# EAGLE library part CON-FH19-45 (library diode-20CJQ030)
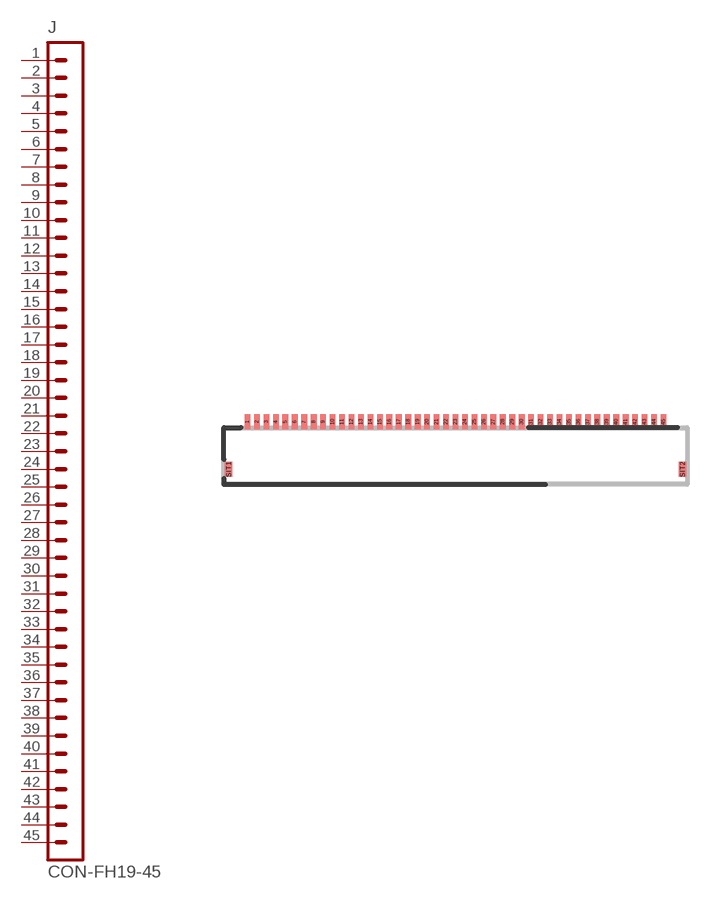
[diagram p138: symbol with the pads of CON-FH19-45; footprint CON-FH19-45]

Designator prefix J

## CON-FH19-45  [CON-FH19-45]
1  1  pas
2  2  pas
3  3  pas
4  4  pas
5  5  pas
6  6  pas
7  7  pas
8  8  pas
9  9  pas
10  10  pas
11  11  pas
12  12  pas
13  13  pas
14  14  pas
15  15  pas
16  16  pas
17  17  pas
18  18  pas
19  19  pas
20  20  pas
21  21  pas
22  22  pas
23  23  pas
24  24  pas
25  25  pas
26  26  pas
27  27  pas
28  28  pas
29  29  pas
30  30  pas
31  31  pas
32  32  pas
33  33  pas
34  34  pas
35  35  pas
36  36  pas
37  37  pas
38  38  pas
39  39  pas
40  40  pas
41  41  pas
42  42  pas
43  43  pas
44  44  pas
45  45  pas

## Footprint CON-FH19-45 (pad centres in mm)
smd 0.3 x 0.8: 1 -10.25,2.54; 2 -9.75,2.54; 3 -9.25,2.54; 4 -8.75,2.54; 5 -8.25,2.54; 6 -7.75,2.54; 7 -7.25,2.54; 8 -6.75,2.54; 9 -6.25,2.54; 10 -5.75,2.54; 11 -5.25,2.54; 12 -4.75,2.54; 13 -4.25,2.54; 14 -3.75,2.54; 15 -3.25,2.54; 16 -2.75,2.54; 17 -2.25,2.54; 18 -1.75,2.54; 19 -1.25,2.54; 20 -0.75,2.54; 21 -0.25,2.54; 22 0.25,2.54; 23 0.75,2.54; 24 1.25,2.54; 25 1.75,2.54; 26 2.25,2.54; 27 2.75,2.54; 28 3.25,2.54; 29 3.75,2.54; 30 4.25,2.54; 31 4.75,2.54; 32 5.25,2.54; 33 5.75,2.54; 34 6.25,2.54; 35 6.75,2.54; 36 7.25,2.54; 37 7.75,2.54; 38 8.25,2.54; 39 8.75,2.54; 40 9.25,2.54; 41 9.75,2.54; 42 10.25,2.54; 43 10.75,2.54; 44 11.25,2.54; 45 11.75,2.54
smd 0.4 x 0.8: SIT1 -11.25,0.04; SIT2 12.75,0.04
